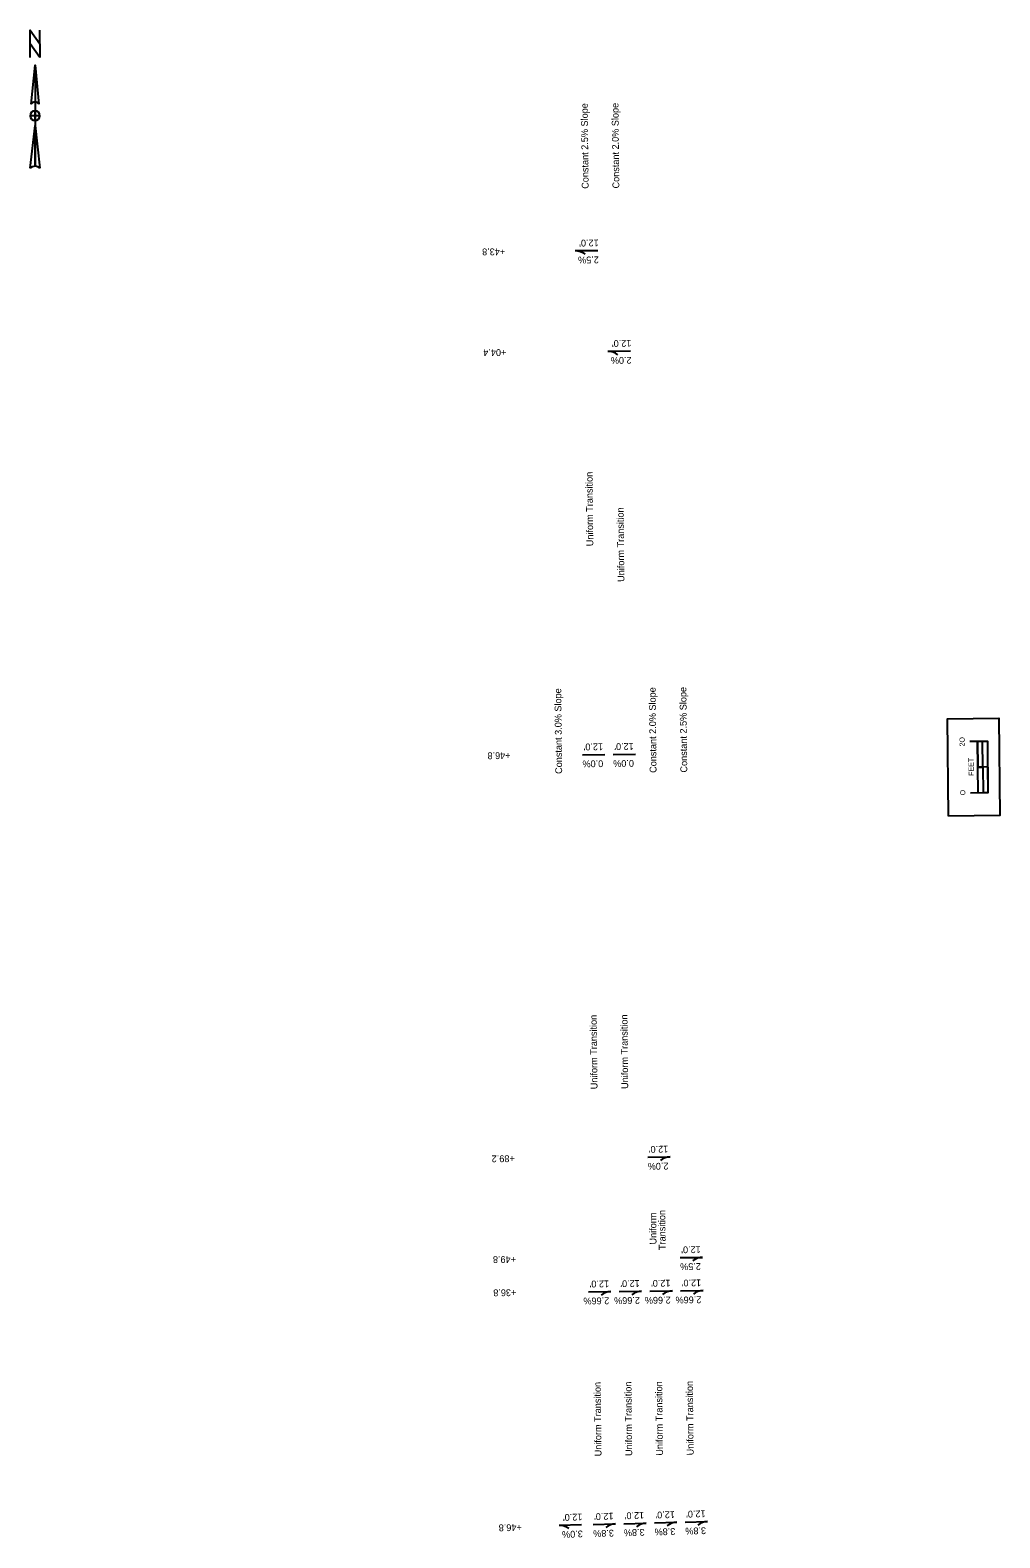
# Model space of a CAD drawing. Extents: x 20505195 to 20506806, y 7965197 to 7979043.
# Drawn here: x 20505195 to 20505574, y 7978454 to 7979043 of the extents above; entities that cross this region are included whole.
import ezdxf

# ---------------------------------------------------------------- set-up
doc = ezdxf.new("R2010")
doc.units = 0
doc.layers.add('Cell', color=7, linetype='Continuous')
doc.layers.add('SheetText', color=7, linetype='Continuous')

msp = doc.modelspace()

# ---------------------------------------------------------------- linework, layer by layer
at = {"layer": 'Cell'}
for p, q in [((20505196.97, 7979029.31), (20505198.49, 7979014.1)), ((20505196.97, 7979029.31), (20505196.97, 7978989.76)), ((20505195.51, 7979014.24), (20505195.79, 7979014.56)), ((20505195.45, 7979014.1), (20505195.45, 7979014.1)), ((20505195.07, 7978989), (20505196.97, 7979005.73)), ((20505196.97, 7979007.64), (20505196.97, 7979007.63))]:
    msp.add_line(p, q, dxfattribs=at)
msp.add_lwpolyline([(20505198.87, 7979032.35), (20505195.07, 7979037.68), (20505195.07, 7979043), (20505198.87, 7979037.68)], close=True, dxfattribs=at)
for points in [[(20505195.07, 7979032.35), (20505195.07, 7979043), (20505198.87, 7979037.68), (20505198.87, 7979043)], [(20505195.45, 7979014.1), (20505196.97, 7979029.31), (20505196.97, 7979014.86)], [(20505196.97, 7979007.63), (20505196.97, 7979009.54), (20505195.07, 7979009.54)], [(20505198.87, 7979009.54), (20505196.97, 7979009.54), (20505196.97, 7979011.44)], [(20505196.97, 7978989.76), (20505196.97, 7979005.73), (20505198.87, 7978989)]]:
    msp.add_lwpolyline(points, dxfattribs=at)
for centre, radius, start, end in [((20505196.97, 7979012.96), 1.9, 90.02039, 143.12574), ((20505196.97, 7979012.96), 1.9, 36.84806, 90.02184), ((20505196.97, 7979009.54), 1.9, 90, 180), ((20505196.97, 7979009.54), 1.9, 180, 270), ((20505196.97, 7979009.54), 1.9, 0, 90), ((20505196.97, 7979009.54), 1.9, 270, 360), ((20505196.97, 7978987.01), 2.76, 89.98939, 133.61895), ((20505196.97, 7978987), 2.76, 46.40206, 90.00064)]:
    msp.add_arc(centre, radius, start, end, dxfattribs=at)
at = {"layer": 'SheetText'}
for p, q in [((20505416.84, 7978956.76), (20505408.07, 7978956.67)), ((20505429.62, 7978917.5), (20505420.85, 7978917.41)), ((20505410.91, 7978759.69), (20505419.68, 7978759.78)), ((20505422.91, 7978759.82), (20505431.68, 7978759.91)), ((20505569.37, 7978754.92), (20505565.37, 7978754.87)), ((20505569.37, 7978754.92), (20505565.37, 7978754.87)), ((20505436.4, 7978602.35), (20505445.17, 7978602.45)), ((20505449.08, 7978563.09), (20505457.85, 7978563.18)), ((20505413.26, 7978549.7), (20505422.03, 7978549.8)), ((20505425.25, 7978549.83), (20505434.02, 7978549.93)), ((20505437.25, 7978549.96), (20505446.02, 7978550.05)), ((20505449.25, 7978550.09), (20505458.02, 7978550.18)), ((20505410.51, 7978458.62), (20505401.75, 7978458.39)), ((20505415.03, 7978458.74), (20505423.8, 7978458.97)), ((20505427.03, 7978459.06), (20505435.8, 7978459.29)), ((20505439.03, 7978459.38), (20505447.79, 7978459.61)), ((20505451.02, 7978459.69), (20505459.79, 7978459.92))]:
    msp.add_line(p, q, dxfattribs=at)
for points in [[(20505553.99, 7978735.74), (20505553.56, 7978773.74), (20505573.55, 7978773.97), (20505573.99, 7978735.97)], [(20505553.99, 7978735.74), (20505553.56, 7978773.74), (20505573.55, 7978773.97), (20505573.99, 7978735.97)], [(20505567.36, 7978754.89), (20505567.25, 7978764.89), (20505565.26, 7978764.87), (20505565.37, 7978754.87)], [(20505569.49, 7978744.92), (20505569.37, 7978754.92), (20505567.36, 7978754.89), (20505567.48, 7978744.89)]]:
    msp.add_lwpolyline(points, close=True, dxfattribs=at)
for points in [[(20505562.49, 7978744.84), (20505569.49, 7978744.92), (20505569.26, 7978764.92), (20505562.26, 7978764.84)], [(20505565.49, 7978744.87), (20505565.26, 7978764.87)]]:
    msp.add_lwpolyline(points, dxfattribs=at)
for centre, start, end in [((20505408.13, 7978950.51), 52.4113, 90.61434), ((20505420.91, 7978911.24), 52.4113, 90.61434), ((20505445.24, 7978596.28), 90.61434, 128.81738), ((20505457.92, 7978557.02), 90.61434, 128.81738), ((20505422.09, 7978543.63), 90.61434, 128.81738), ((20505434.09, 7978543.76), 90.61434, 128.81738), ((20505446.09, 7978543.89), 90.61434, 128.81738), ((20505458.09, 7978544.02), 90.61434, 128.81738), ((20505401.91, 7978452.23), 53.31032, 91.51336), ((20505423.96, 7978452.81), 91.51336, 129.7164), ((20505435.96, 7978453.13), 91.51336, 129.7164), ((20505447.96, 7978453.45), 91.51336, 129.7164), ((20505459.95, 7978453.76), 91.51336, 129.7164)]:
    msp.add_arc(centre, 6.16, start, end, dxfattribs=at)

# ---------------------------------------------------------------- texts
for s, height, rotation, p in [('Constant 2.5% Slope', 2.664, 90.61434, (20505413.3, 7978980.99)), ('Constant 2.0% Slope', 2.664, 90.61434, (20505425.3, 7978981.12)), ("12.0'", 2.664, 180.71706, (20505417.22, 7978961.16)), ('+43.8', 2.664, 180.61343, (20505380.68, 7978957.71)), ('2.5%', 2.664, 180.71706, (20505417.29, 7978954.54)), ("12.0'", 2.664, 180.71706, (20505430, 7978921.9)), ('+04.4', 2.664, 180.61343, (20505381.13, 7978918.31)), ('2.0%', 2.664, 180.71706, (20505430.07, 7978915.28)), ('Uniform Transition', 2.664, 90.61434, (20505415.13, 7978841.25)), ('Uniform Transition', 2.664, 90.61434, (20505427.28, 7978827.31)), ('Constant 3.0% Slope', 2.664, 90.61434, (20505402.95, 7978752.23)), ('Constant 2.0% Slope', 2.664, 90.61434, (20505439.84, 7978752.63)), ('Constant 2.5% Slope', 2.664, 90.61434, (20505451.84, 7978752.76)), ('+46.8', 2.664, 180.61343, (20505382.79, 7978760.72)), ("12.0'", 2.664, 180.71706, (20505418.93, 7978764.17)), ("12.0'", 2.664, 180.71706, (20505430.93, 7978764.3)), ('2O', 2, 90.6619, (20505560.28, 7978762.94)), ('0.0%', 2.664, 180.71706, (20505419, 7978757.55)), ('0.0%', 2.664, 180.71706, (20505431, 7978757.68)), ('FEET', 2, 90.6619, (20505563.81, 7978751.47)), ('O', 2, 90.6619, (20505560.5, 7978743.83)), ('Uniform Transition', 2.664, 90.61434, (20505416.77, 7978628.94)), ('Uniform Transition', 2.664, 90.61434, (20505428.77, 7978629.07)), ('+89.2', 2.664, 180.61343, (20505384.43, 7978603.13)), ("12.0'", 2.664, 180.71706, (20505444.42, 7978606.84)), ('2.0%', 2.664, 180.71706, (20505444.49, 7978600.21)), ('Uniform', 2.664, 90.61434, (20505439.83, 7978568.23)), ('Transition', 2.664, 90.61434, (20505443.4, 7978566.08)), ("12.0'", 2.664, 180.71706, (20505457.1, 7978567.57)), ('+49.8', 2.664, 180.61343, (20505384.9, 7978563.73)), ('2.5%', 2.664, 180.71706, (20505457.17, 7978560.95)), ("12.0'", 2.664, 180.71706, (20505445.28, 7978554.44)), ("12.0'", 2.664, 180.71706, (20505457.28, 7978554.57)), ('+36.8', 2.664, 180.61343, (20505385.04, 7978550.73)), ("12.0'", 2.664, 180.71706, (20505421.28, 7978554.18)), ("12.0'", 2.664, 180.71706, (20505433.28, 7978554.31)), ('2.66%', 2.664, 180.71706, (20505421.35, 7978547.56)), ('2.66%', 2.664, 180.71706, (20505433.35, 7978547.69)), ('2.66%', 2.664, 180.71706, (20505445.35, 7978547.82)), ('2.66%', 2.664, 180.71706, (20505457.34, 7978547.95)), ('Uniform Transition', 2.664, 90.61434, (20505418.34, 7978485.41)), ('Uniform Transition', 2.664, 90.61434, (20505430.34, 7978485.54)), ('Uniform Transition', 2.664, 90.61434, (20505442.34, 7978485.66)), ('Uniform Transition', 2.664, 90.61434, (20505454.34, 7978485.79)), ("12.0'", 2.664, 181.61608, (20505410.83, 7978463.03)), ("12.0'", 2.664, 181.61608, (20505422.99, 7978463.35)), ("12.0'", 2.664, 181.61608, (20505434.98, 7978463.67)), ("12.0'", 2.664, 181.61608, (20505446.98, 7978463.98)), ("12.0'", 2.664, 181.61608, (20505458.97, 7978464.3)), ('+46.8', 2.664, 181.51336, (20505387.15, 7978458.97)), ('3.0%', 2.664, 181.61608, (20505411, 7978456.41)), ('3.8%', 2.664, 181.61608, (20505423.16, 7978456.73)), ('3.8%', 2.664, 181.61608, (20505435.15, 7978457.04)), ('3.8%', 2.664, 181.61608, (20505447.15, 7978457.36)), ('3.8%', 2.664, 181.61608, (20505459.15, 7978457.68))]:
    msp.add_text(s, height=height, rotation=rotation, dxfattribs=at).set_placement(p)

doc.saveas('drawing.dxf')
